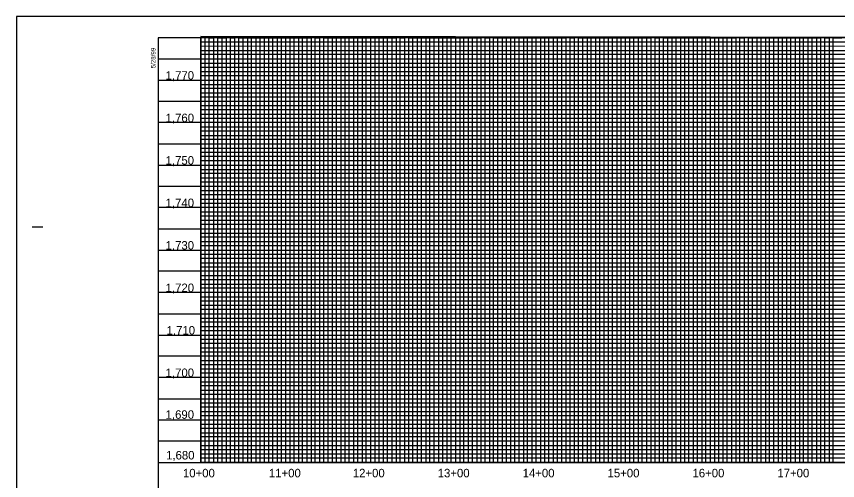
# Model space of a CAD drawing. Extents: x 505602 to 507548, y 483109 to 484209.
# Drawn here: x 505602 to 506569, y 483662 to 484209 of the extents above; entities that cross this region are included whole.
import ezdxf

# ---------------------------------------------------------------- set-up
doc = ezdxf.new("R2010")
doc.units = 0
for name, color, linetype in [('Exist Vertical Profile Vertical Axis Label', 7, 'Continuous'), ('Scratch_Level_5', 7, 'Continuous'), ('Sheet Layout Profile Border Port 1', 7, 'Continuous'), ('Sheet Plot Border Outside CELL', 7, 'Continuous'), ('Sheet Profile CELL', 7, 'Continuous'), ('Sheet Profile Grid Major CELL', 7, 'Continuous'), ('Sheet Profile Grid Middle CELL', 7, 'Continuous'), ('Sheet Profile Grid Minor CELL', 7, 'Continuous')]:
    doc.layers.add(name, color=color, linetype=linetype)

msp = doc.modelspace()

# ---------------------------------------------------------------- linework, layer by layer
at = {"layer": 'Scratch_Level_5'}
msp.add_lwpolyline([(505819.08, 484183.83), (506824.84, 484183.83), (506824.84, 484134), (506919.08, 484133.22), (506919.3, 483683.71), (505819.08, 483683.71)], close=True, dxfattribs=at)
msp.add_lwpolyline([(505819.08, 484022.66), (505819.08, 483683.71), (507219.08, 483683.71), (507219.08, 484022.66)], dxfattribs=at)
at = {"layer": 'Sheet Layout Profile Border Port 1'}
msp.add_lwpolyline([(505819.08, 484185.09), (505819.08, 483683.71), (507019.08, 483683.71), (507019.08, 484183.71), (507019.08, 484183.71), (507019.08, 484183.71)], close=True, dxfattribs=at)
at = {"layer": 'Sheet Plot Border Outside CELL'}
msp.add_lwpolyline([(505602.08, 483108.71), (507286.08, 483108.71), (507286.08, 484208.71), (505602.08, 484208.71)], close=True, dxfattribs=at)
at = {"layer": 'Sheet Profile CELL'}
for p, q in [((505620.58, 483961.21), (505633.08, 483961.21)), ((505769.08, 483683.71), (507269.08, 483683.71))]:
    msp.add_line(p, q, dxfattribs=at)
msp.add_lwpolyline([(507269.08, 484183.71), (505769.08, 484183.71), (505769.08, 483133.71), (507269.08, 483133.71)], close=True, dxfattribs=at)
at = {"layer": 'Sheet Profile Grid Major CELL'}
for points in [[(505819.08, 484183.71), (505819.08, 483683.71), (505869.08, 483683.71), (505869.08, 484183.71), (505919.08, 484183.71), (505919.08, 483683.71), (505969.08, 483683.71), (505969.08, 484183.71), (506019.08, 484183.71), (506019.08, 483683.71), (506069.08, 483683.71), (506069.08, 484183.71), (506119.08, 484183.71), (506119.08, 483683.71), (506169.08, 483683.71), (506169.08, 484183.71), (506219.08, 484183.71), (506219.08, 483683.71), (506269.08, 483683.71), (506269.08, 484183.71), (506319.08, 484183.71), (506319.08, 483683.71), (506369.08, 483683.71), (506369.08, 484183.71), (506419.08, 484183.71), (506419.08, 483683.71), (506469.08, 483683.71), (506469.08, 484183.71), (506519.08, 484183.71), (506519.08, 483683.71), (506569.08, 483683.71)], [(505769.08, 484133.71), (507069.08, 484133.71)], [(507069.08, 484083.71), (505769.08, 484083.71), (505769.08, 484033.71), (507069.08, 484033.71)], [(507269.08, 483983.71), (505769.08, 483983.71), (505769.08, 483933.71), (507269.08, 483933.71)], [(507269.08, 483883.71), (505769.08, 483883.71), (505769.08, 483833.71), (507269.08, 483833.71)], [(507269.08, 483783.71), (505769.08, 483783.71), (505769.08, 483783.71), (505769.08, 483733.71), (507269.08, 483733.71)]]:
    msp.add_lwpolyline(points, dxfattribs=at)
at = {"layer": 'Sheet Profile Grid Middle CELL'}
msp.add_line((505769.08, 484158.71), (507069.03, 484158.71), dxfattribs=at)
for points in [[(505844.08, 484183.71), (505844.08, 483683.71), (505894.08, 483683.71), (505894.08, 484183.71), (505944.08, 484183.71), (505944.08, 483683.71), (505994.08, 483683.71), (505994.08, 484183.71), (506044.08, 484183.71), (506044.08, 483683.71), (506094.08, 483683.71), (506094.08, 484183.71), (506144.08, 484183.71), (506144.08, 483683.71), (506194.08, 483683.71), (506194.08, 484183.71), (506244.08, 484183.71), (506244.08, 483683.71), (506294.08, 483683.71), (506294.08, 484183.71), (506344.08, 484183.71), (506344.08, 483683.71), (506394.08, 483683.71), (506394.08, 483683.71), (506394.08, 484183.71), (506444.08, 484183.71), (506444.08, 483683.71), (506494.08, 483683.71), (506494.08, 484183.71), (506544.08, 484183.71), (506544.08, 483683.71), (506594.08, 483683.71)], [(507069.08, 484108.71), (505769.08, 484108.71), (505769.08, 484058.71), (507069.08, 484058.71)], [(507269.08, 484008.71), (505769.08, 484008.71), (505769.08, 483958.71), (507094.08, 483958.71)], [(507269.08, 483908.71), (505769.08, 483908.71), (505769.08, 483858.71), (507269.08, 483858.71)], [(507269.08, 483808.71), (505769.08, 483808.71), (505769.08, 483758.71), (507269.08, 483758.71)], [(507269.08, 483708.71), (505769.08, 483708.71)]]:
    msp.add_lwpolyline(points, dxfattribs=at)
at = {"layer": 'Sheet Profile Grid Minor CELL'}
for p, q in [((505819.08, 484178.71), (507069.08, 484178.71)), ((505819.08, 484173.71), (505819.08, 484173.71)), ((507069.08, 484173.71), (505819.08, 484173.36)), ((505819.08, 484168.71), (507069.08, 484168.71)), ((507069.03, 484048.71), (505819.08, 484048.71)), ((507069.08, 484043.71), (505819.08, 484043.71)), ((507069.08, 484038.71), (505819.08, 484038.71)), ((505819.08, 484028.71), (507069.08, 484028.71)), ((507069.08, 484023.71), (505819.08, 484023.71)), ((505819.08, 484018.71), (507219.08, 484018.71)), ((507219.08, 483998.71), (505819.08, 483998.71)), ((505819.08, 483993.71), (507219.08, 483993.71)), ((507219.08, 483973.71), (505819.08, 483973.71)), ((505819.08, 483968.71), (507219.08, 483968.71)), ((507219.08, 483948.71), (505819.08, 483948.71)), ((505819.08, 483943.71), (507219.08, 483943.71)), ((507219.08, 483938.71), (505819.08, 483938.71)), ((505819.08, 483928.71), (507219.08, 483928.71)), ((507219.08, 483923.71), (505819.08, 483923.71)), ((505819.08, 483918.71), (507219.08, 483918.71)), ((507219.08, 483913.71), (505819.08, 483913.71)), ((505819.08, 483903.71), (507219.08, 483903.71)), ((507219.08, 483898.71), (505819.08, 483898.71)), ((505819.08, 483893.71), (507219.08, 483893.71)), ((507219.08, 483888.71), (505819.08, 483888.71)), ((505819.08, 483878.71), (507219.08, 483878.71)), ((507219.08, 483873.71), (505819.08, 483873.71)), ((505819.08, 483868.71), (507219.08, 483868.71)), ((507219.08, 483863.71), (505819.08, 483863.71)), ((505819.08, 483853.71), (507219.08, 483853.71)), ((507219.08, 483848.71), (505819.08, 483848.71)), ((505819.08, 483843.71), (507219.08, 483843.71)), ((507219.08, 483838.71), (505819.08, 483838.71)), ((505819.08, 483828.71), (507219.08, 483828.71)), ((507219.08, 483823.71), (505819.08, 483823.71)), ((505819.08, 483818.71), (507219.08, 483818.71)), ((507219.08, 483813.71), (505819.08, 483813.71)), ((505819.08, 483803.71), (507219.08, 483803.71)), ((507219.08, 483798.71), (505819.08, 483798.71)), ((507219.08, 483793.71), (505819.08, 483793.71)), ((507219.08, 483788.71), (505819.08, 483788.71)), ((505819.08, 483778.71), (507219.08, 483778.71)), ((507219.08, 483773.71), (505819.08, 483773.71)), ((505819.08, 483768.71), (507219.08, 483768.71)), ((507219.08, 483763.71), (505819.08, 483763.71)), ((505819.08, 483753.71), (507219.08, 483753.71)), ((507219.08, 483748.71), (505819.08, 483748.71)), ((505819.08, 483743.71), (507219.08, 483743.71)), ((507219.08, 483738.71), (505819.08, 483738.71)), ((505819.08, 483728.71), (507219.08, 483728.71)), ((507219.08, 483723.71), (505819.08, 483723.71)), ((505819.08, 483718.71), (507219.08, 483718.71)), ((507219.08, 483713.71), (505819.08, 483713.71)), ((505819.08, 483703.71), (507219.08, 483703.71)), ((507219.08, 483698.71), (505819.08, 483698.71)), ((505819.08, 483693.71), (507219.08, 483693.71))]:
    msp.add_line(p, q, dxfattribs=at)
for points in [[(505824.08, 484183.71), (505824.08, 483683.71), (505829.08, 483683.71), (505829.08, 484183.71), (505834.08, 484183.71), (505834.08, 483683.71), (505839.08, 483683.71), (505839.08, 484183.71), (505849.08, 484183.71), (505849.08, 483683.71), (505854.08, 483683.71), (505854.08, 484183.71), (505859.08, 484183.71), (505859.08, 483683.71), (505864.08, 483683.71), (505874.08, 483683.71), (505879.08, 483683.71), (505879.08, 484183.71), (505884.08, 484183.71), (505884.08, 483683.71), (505889.08, 483683.71), (505889.08, 484183.71), (505899.08, 484183.71), (505899.08, 483683.71), (505904.08, 483683.71), (505904.08, 484183.71), (505909.08, 484183.71), (505909.08, 483683.71), (505914.08, 483683.71), (505914.08, 484183.71), (505924.08, 484183.71), (505924.08, 483683.71), (505929.08, 483683.71), (505929.08, 484183.71), (505934.08, 484183.71), (505934.08, 483683.71), (505939.08, 483683.71), (505939.08, 484183.71), (505949.08, 484183.71), (505949.08, 483683.71), (505954.08, 483683.71), (505954.08, 484183.71), (505959.08, 484183.71), (505959.08, 483683.71), (505964.08, 483683.71), (505964.08, 484183.71), (505974.08, 484183.71), (505974.08, 483683.71), (505979.08, 483683.71), (505979.08, 484183.71), (505984.08, 484183.71), (505984.08, 483683.71), (505989.08, 483683.71), (505989.08, 484183.71), (505999.08, 484183.71), (505999.08, 483683.71), (506004.08, 483683.71), (506004.08, 484183.71), (506009.08, 484183.71), (506009.08, 483683.71), (506014.08, 483683.71), (506014.08, 484183.71), (506024.08, 484183.71), (506024.08, 483683.71), (506029.08, 483683.71), (506029.08, 484183.71), (506034.08, 484183.71), (506034.08, 483683.71)], [(505864.08, 483683.71), (505864.08, 484183.71), (505874.08, 484183.71), (505874.08, 483683.71)], [(506034.08, 483683.71), (506039.08, 483683.71), (506039.08, 484183.71), (506049.08, 484183.71), (506049.08, 483683.71), (506054.08, 483683.71), (506054.08, 484183.71), (506059.08, 484183.71), (506059.08, 483683.71), (506064.08, 483683.71), (506064.08, 484183.71), (506074.08, 484183.71), (506074.08, 483683.71), (506079.08, 483683.71), (506079.08, 484183.71), (506084.08, 484183.71), (506084.08, 483683.71), (506089.08, 483683.71), (506089.08, 484183.71), (506099.08, 484183.71), (506099.08, 483683.71), (506104.08, 483683.71), (506104.08, 484183.71), (506109.08, 484183.71), (506109.08, 483683.71), (506114.08, 483683.71), (506114.08, 484183.71), (506124.08, 484183.71), (506124.08, 483683.71), (506129.08, 483683.71), (506129.08, 484183.71), (506134.08, 484183.71), (506134.08, 483683.71), (506139.08, 483683.71), (506139.08, 484183.71), (506149.08, 484183.71), (506149.08, 483683.71), (506154.08, 483683.71), (506154.08, 484183.71), (506159.08, 484183.71), (506159.08, 483683.71), (506164.08, 483683.71), (506164.08, 484183.71), (506174.08, 484183.71), (506174.08, 483683.71), (506179.08, 483683.71), (506179.08, 484183.71), (506184.08, 484183.71), (506184.08, 483683.71), (506189.08, 483683.71), (506189.08, 484183.71), (506199.08, 484183.71), (506199.08, 483683.71), (506204.08, 483683.71), (506204.08, 484183.71), (506209.08, 484183.71), (506209.08, 483683.71), (506214.08, 483683.71), (506214.08, 484183.71), (506224.08, 484183.71), (506224.08, 483683.71), (506229.08, 483683.71), (506229.08, 484183.71), (506234.08, 484183.71), (506234.08, 483683.71), (506239.08, 483683.71), (506239.08, 484183.71), (506249.08, 484183.71), (506249.08, 483683.71), (506254.08, 483683.71), (506254.08, 484183.71), (506259.08, 484183.71), (506259.08, 483683.71), (506264.08, 483683.71), (506264.08, 484183.71), (506274.08, 484183.71), (506274.08, 483683.71), (506279.08, 483683.71), (506279.08, 484183.71), (506284.08, 484183.71), (506284.08, 483683.71), (506289.08, 483683.71), (506289.08, 484183.71), (506299.08, 484183.71), (506299.08, 483683.71), (506304.08, 483683.71), (506304.08, 484183.71), (506309.08, 484183.71), (506309.08, 483683.71), (506314.08, 483683.71), (506314.08, 484183.71), (506324.08, 484183.71), (506324.08, 483683.71), (506329.08, 483683.71), (506329.08, 484183.71), (506334.08, 484183.71), (506334.08, 483683.71), (506339.08, 483683.71), (506339.08, 484183.71), (506349.08, 484183.71)], [(506349.08, 484183.71), (506349.08, 483683.71), (506354.08, 483683.71), (506354.08, 484183.71), (506359.08, 484183.71), (506359.08, 483683.71), (506364.08, 483683.71), (506364.08, 484183.71), (506374.08, 484183.71), (506374.08, 483683.71), (506379.08, 483683.71), (506379.08, 484183.71), (506384.08, 484183.71), (506384.08, 483683.71), (506389.08, 483683.71), (506389.08, 484183.71), (506399.08, 484183.71), (506399.08, 483683.71), (506404.08, 483683.71), (506404.08, 484183.71), (506409.08, 484183.71), (506409.08, 483683.71), (506414.08, 483683.71), (506414.08, 484183.71), (506424.08, 484183.71), (506424.08, 483683.71), (506429.08, 483683.71), (506429.08, 484183.71), (506434.08, 484183.71), (506434.08, 483683.71), (506439.08, 483683.71), (506439.08, 484183.71), (506449.08, 484183.71), (506449.08, 483683.71), (506454.08, 483683.71), (506454.08, 484183.71), (506459.08, 484183.71), (506459.08, 483683.71), (506464.08, 483683.71), (506464.08, 484183.71), (506474.08, 484183.71), (506474.08, 483683.71), (506474.08, 483683.71), (506479.08, 483683.71), (506479.08, 484183.71), (506484.08, 484183.71), (506484.08, 483683.71), (506489.08, 483683.71), (506489.08, 484183.71), (506499.08, 484183.71), (506499.08, 483683.71), (506504.08, 483683.71), (506504.08, 484183.71), (506509.08, 484183.71), (506509.08, 483683.71), (506514.08, 483683.71), (506514.08, 484183.71), (506524.08, 484183.71), (506524.08, 483683.71), (506529.08, 483683.71), (506529.08, 484183.71), (506534.08, 484183.71), (506534.08, 483683.71), (506539.08, 483683.71), (506539.08, 484183.71), (506549.08, 484183.71), (506549.08, 483683.71), (506554.08, 483683.71), (506554.08, 484183.71), (506559.08, 484183.71), (506559.08, 483683.71), (506564.08, 483683.71), (506564.08, 484183.71), (506574.08, 484183.71)], [(507069.08, 484163.71), (505819.08, 484163.71), (505819.08, 484153.71), (507069.08, 484153.71)], [(507069.03, 484148.71), (505819.08, 484148.71), (505819.08, 484143.71), (507069.08, 484143.71)], [(507069.08, 484138.71), (505819.08, 484138.71), (505819.08, 484128.71), (507069.08, 484128.71)], [(507069.08, 484123.71), (505819.08, 484123.71), (505819.08, 484118.71), (507069.08, 484118.71)], [(507069.08, 484113.71), (505819.08, 484113.71), (505819.08, 484103.71), (507069.08, 484103.71)], [(507069.08, 484098.71), (505819.08, 484098.71), (505819.08, 484093.71), (507069.08, 484093.71)], [(507069.08, 484088.71), (505819.08, 484088.71), (505819.08, 484078.71), (507069.08, 484078.71)], [(507069.08, 484073.61), (505819.18, 484073.61), (505819.18, 484068.71), (507069.08, 484068.71)], [(507069.08, 484063.71), (505819.08, 484063.71), (505819.08, 484053.71), (507069.08, 484053.71)], [(507219.08, 484013.71), (505819.08, 484013.71), (505819.08, 484003.71), (507219.08, 484003.71)], [(507219.08, 483988.71), (505819.08, 483988.71), (505819.08, 483978.71), (507219.08, 483978.71)], [(507219.08, 483963.71), (505819.08, 483963.71), (505819.08, 483953.71), (507219.08, 483953.71)], [(507219.08, 483688.71), (505819.08, 483688.71)]]:
    msp.add_lwpolyline(points, dxfattribs=at)

# ---------------------------------------------------------------- texts
at = {"layer": 'Exist Vertical Profile Vertical Axis Label'}
for s, p in [('1,770', (505777.78, 484134.28)), ('1,760', (505777.78, 484084.28)), ('1,750', (505777.78, 484034.28)), ('1,740', (505777.78, 483984.28)), ('1,730', (505777.78, 483934.28)), ('1,720', (505777.78, 483884.28)), ('1,710', (505778.97, 483834.28)), ('1,700', (505777.78, 483784.28)), ('1,690', (505777.78, 483735.12)), ('1,680', (505778.32, 483687.23)), ('10+00', (505798.21, 483666.21)), ('11+00', (505899.41, 483666.21)), ('12+00', (505998.21, 483666.21)), ('13+00', (506098.21, 483666.21)), ('14+00', (506198.21, 483666.21)), ('15+00', (506298.21, 483666.21)), ('16+00', (506398.21, 483666.21)), ('17+00', (506498.21, 483666.21))]:
    msp.add_text(s, height=10, dxfattribs=at).set_placement(p)
at = {"layer": 'Sheet Profile CELL'}
msp.add_text('5/28/99', height=5.25, rotation=90, dxfattribs=at).set_placement((505765.84, 484147.62))

doc.saveas('drawing.dxf')
